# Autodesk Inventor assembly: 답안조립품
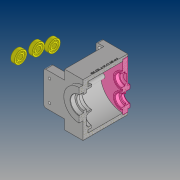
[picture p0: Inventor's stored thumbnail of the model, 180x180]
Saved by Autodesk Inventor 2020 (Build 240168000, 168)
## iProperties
Created: 2020-07
Part Number: 답안조립품
Document SubType Name: Assembly
Designer: PC312-
Author: PC312-
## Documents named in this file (4)
- C:\Users\PC312-\Desktop\700718V1006\답안조립품.iam
- C:\Users\PC312-\Desktop\700718V1006\본체.ipt
- C:\Users\PC312-\Desktop\700718V1006\베어링 608.ipt
- C:\Users\PC312-\Desktop\700718V1006\커버.ipt
